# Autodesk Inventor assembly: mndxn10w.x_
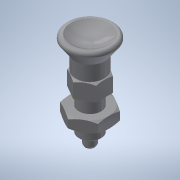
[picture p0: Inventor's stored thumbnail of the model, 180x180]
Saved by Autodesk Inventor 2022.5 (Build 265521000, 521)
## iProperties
Part Number: mndxn10w.x_
Material: 一般
Document SubType Name: Assembly
Designer: ImaoCorp
Sending System: SOLIDWORKS 2017-2017317
MC: AMD64
MC_MODEL: Intel64 Family 6 Model 60 Stepping 3, GenuineIntel
OS: Windows_NT
FRU: Parasolid Version 29.0, build 201,  4-17-2017
FORMAT: text
GUISE: transmit
KEY: mndxn10w
FILE: mndxn10w.x_t
DATE: Fri Jul 26 11:48:05 2019
Author: ImaoCorp
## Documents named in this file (3)
- X:\14_SW2022-Inv2022\00_全2023-1023新製品(TCC)まで\m\mndxn10w\MNDXN10W.iam
- X:\14_SW2022-Inv2022\00_全2023-1023新製品(TCC)まで\m\mndxn10w\mndxn10w_01.ipt
- X:\14_SW2022-Inv2022\00_全2023-1023新製品(TCC)まで\m\mndxn10w\mndxn10w_02.ipt
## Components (2 placed, 2 different names)
1. mndxn10w_01
2. mndxn10w_02
